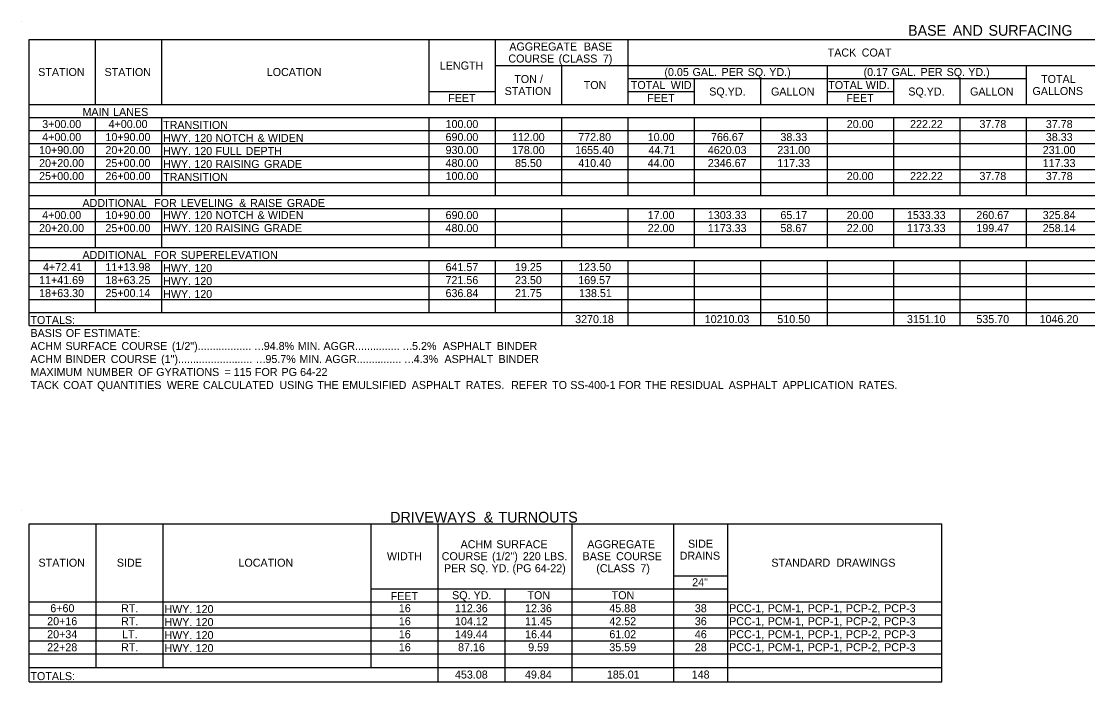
# Model space of a CAD drawing. Extents: x 1940653 to 1945779, y 534266 to 535271.
# Drawn here: x 1942440 to 1943159, y 534789 to 535235 of the extents above; entities that cross this region are included whole.
import ezdxf

# ---------------------------------------------------------------- set-up
doc = ezdxf.new("R2010")
doc.units = 0
doc.layers.add('Default', color=7, linetype='Continuous')
doc.layers.add('R_Logo', color=7, linetype='Continuous')

msp = doc.modelspace()

# ---------------------------------------------------------------- linework, layer by layer
at = {"layer": 'Default'}
for p, q in [((1942444.79, 535222.25), (1943743.93, 535222.25)), ((1942444.79, 535029.2), (1942444.79, 535222.25)), ((1942444.79, 535029.2), (1942444.79, 535222.25)), ((1942489.55, 535178.37), (1942489.55, 535222.25)), ((1942534.3, 535178.37), (1942534.3, 535222.25)), ((1942714.63, 535178.37), (1942714.63, 535222.25)), ((1942759.38, 535178.37), (1942759.38, 535222.25)), ((1942848.88, 535178.37), (1942848.88, 535222.25)), ((1942759.38, 535204.7), (1943743.93, 535204.7)), ((1942804.13, 535178.37), (1942804.13, 535204.7)), ((1942983.14, 535178.37), (1942983.14, 535204.7)), ((1943117.4, 535178.37), (1943117.4, 535204.7)), ((1942848.88, 535195.92), (1943117.4, 535195.92)), ((1942893.64, 535178.37), (1942893.64, 535195.92)), ((1942938.39, 535178.37), (1942938.39, 535195.92)), ((1943027.89, 535178.37), (1943027.89, 535195.92)), ((1943072.65, 535178.37), (1943072.65, 535195.92)), ((1942714.63, 535187.15), (1942759.38, 535187.15)), ((1942759.38, 535178.37), (1942759.38, 535187.15)), ((1942848.88, 535187.15), (1942893.64, 535187.15)), ((1942893.64, 535178.37), (1942893.64, 535187.15)), ((1942983.14, 535187.15), (1943027.89, 535187.15)), ((1943027.89, 535178.37), (1943027.89, 535187.15)), ((1942444.79, 535178.37), (1943743.93, 535178.37)), ((1942759.38, 535178.37), (1942893.64, 535178.37)), ((1942893.64, 535178.37), (1943027.89, 535178.37)), ((1943027.89, 535178.37), (1943072.65, 535178.37)), ((1943072.65, 535178.37), (1943206.9, 535178.37)), ((1942444.79, 535169.6), (1943743.93, 535169.6)), ((1942489.55, 535116.95), (1942489.55, 535169.6)), ((1942489.55, 535116.95), (1942489.55, 535169.6)), ((1942534.3, 535169.6), (1942714.63, 535169.6)), ((1942534.3, 535116.95), (1942534.3, 535169.6)), ((1942534.3, 535116.95), (1942534.3, 535169.6)), ((1942714.63, 535116.95), (1942714.63, 535169.6)), ((1942714.63, 535116.95), (1942714.63, 535169.6)), ((1942759.38, 535116.95), (1942759.38, 535169.6)), ((1942759.38, 535116.95), (1942759.38, 535169.6)), ((1942804.13, 535116.95), (1942804.13, 535169.6)), ((1942804.13, 535116.95), (1942804.13, 535169.6)), ((1942848.88, 535116.95), (1942848.88, 535169.6)), ((1942848.88, 535116.95), (1942848.88, 535169.6)), ((1942893.64, 535116.95), (1942893.64, 535169.6)), ((1942893.64, 535116.95), (1942893.64, 535169.6)), ((1942938.39, 535116.95), (1942938.39, 535169.6)), ((1942938.39, 535116.95), (1942938.39, 535169.6)), ((1942983.14, 535116.95), (1942983.14, 535169.6)), ((1942983.14, 535116.95), (1942983.14, 535169.6)), ((1943027.89, 535116.95), (1943027.89, 535169.6)), ((1943027.89, 535116.95), (1943027.89, 535169.6)), ((1943072.65, 535116.95), (1943072.65, 535169.6)), ((1943072.65, 535116.95), (1943072.65, 535169.6)), ((1943117.4, 535116.95), (1943117.4, 535169.6)), ((1943117.4, 535116.95), (1943117.4, 535169.6)), ((1942444.79, 535160.82), (1943743.93, 535160.82)), ((1942444.79, 535152.05), (1943743.93, 535152.05)), ((1942444.79, 535143.27), (1943743.93, 535143.27)), ((1942444.79, 535134.5), (1943743.93, 535134.5)), ((1942444.79, 535125.72), (1943743.93, 535125.72)), ((1942444.79, 535116.95), (1942893.64, 535116.95)), ((1942444.79, 535116.95), (1943743.93, 535116.95)), ((1942893.64, 535116.95), (1942983.14, 535116.95)), ((1942983.14, 535116.95), (1943027.89, 535116.95)), ((1943027.89, 535116.95), (1943162.15, 535116.95)), ((1942444.79, 535108.17), (1943743.93, 535108.17)), ((1942489.55, 535081.85), (1942489.55, 535108.17)), ((1942489.55, 535081.85), (1942489.55, 535108.17)), ((1942534.3, 535081.85), (1942534.3, 535108.17)), ((1942534.3, 535081.85), (1942534.3, 535108.17)), ((1942714.63, 535081.85), (1942714.63, 535108.17)), ((1942714.63, 535081.85), (1942714.63, 535108.17)), ((1942759.38, 535081.85), (1942759.38, 535108.17)), ((1942759.38, 535081.85), (1942759.38, 535108.17)), ((1942804.13, 535081.85), (1942804.13, 535108.17)), ((1942804.13, 535081.85), (1942804.13, 535108.17)), ((1942848.88, 535081.85), (1942848.88, 535108.17)), ((1942848.88, 535081.85), (1942848.88, 535108.17)), ((1942893.64, 535081.85), (1942893.64, 535108.17)), ((1942893.64, 535081.85), (1942893.64, 535108.17)), ((1942938.39, 535081.85), (1942938.39, 535108.17)), ((1942938.39, 535081.85), (1942938.39, 535108.17)), ((1942983.14, 535081.85), (1942983.14, 535108.17)), ((1942983.14, 535081.85), (1942983.14, 535108.17)), ((1943027.89, 535081.85), (1943027.89, 535108.17)), ((1943027.89, 535081.85), (1943027.89, 535108.17)), ((1943072.65, 535081.85), (1943072.65, 535108.17)), ((1943072.65, 535081.85), (1943072.65, 535108.17)), ((1943117.4, 535081.85), (1943117.4, 535108.17)), ((1943117.4, 535081.85), (1943117.4, 535108.17)), ((1942444.79, 535099.4), (1943743.93, 535099.4)), ((1942444.79, 535090.62), (1943743.93, 535090.62)), ((1942444.79, 535081.85), (1942848.88, 535081.85)), ((1942444.79, 535081.85), (1943743.93, 535081.85)), ((1942848.88, 535081.85), (1943117.4, 535081.85)), ((1943117.4, 535081.85), (1943564.92, 535081.85)), ((1942444.79, 535073.07), (1943743.93, 535073.07)), ((1942489.55, 535037.97), (1942489.55, 535073.07)), ((1942489.55, 535037.97), (1942489.55, 535073.07)), ((1942534.3, 535037.97), (1942534.3, 535073.07)), ((1942534.3, 535037.97), (1942534.3, 535073.07)), ((1942714.63, 535037.97), (1942714.63, 535073.07)), ((1942714.63, 535037.97), (1942714.63, 535073.07)), ((1942759.38, 535037.97), (1942759.38, 535073.07)), ((1942759.38, 535037.97), (1942759.38, 535073.07)), ((1942804.13, 535029.2), (1942804.13, 535073.07)), ((1942804.13, 535029.2), (1942804.13, 535073.07)), ((1942848.88, 535029.2), (1942848.88, 535073.07)), ((1942848.88, 535029.2), (1942848.88, 535073.07)), ((1942893.64, 535029.2), (1942893.64, 535073.07)), ((1942893.64, 535029.2), (1942893.64, 535073.07)), ((1942938.39, 535037.97), (1942938.39, 535073.07)), ((1942938.39, 535029.2), (1942938.39, 535073.07)), ((1942983.14, 535037.97), (1942983.14, 535073.07)), ((1942983.14, 535029.2), (1942983.14, 535073.07)), ((1943027.89, 535029.2), (1943027.89, 535073.07)), ((1943027.89, 535029.2), (1943027.89, 535073.07)), ((1943072.65, 535037.97), (1943072.65, 535073.07)), ((1943072.65, 535029.2), (1943072.65, 535073.07)), ((1943117.4, 535037.97), (1943117.4, 535073.07)), ((1943117.4, 535029.2), (1943117.4, 535073.07)), ((1942444.79, 535064.3), (1943743.93, 535064.3)), ((1942444.79, 535055.52), (1943743.93, 535055.52)), ((1942444.79, 535046.75), (1943743.93, 535046.75)), ((1942444.79, 535037.97), (1943743.93, 535037.97)), ((1942444.79, 535029.2), (1943743.93, 535029.2)), ((1942444.79, 534895.53), (1943060.36, 534895.53)), ((1942444.79, 534788.91), (1942444.79, 534895.53)), ((1942444.79, 534788.91), (1942444.79, 534895.53)), ((1942489.99, 534798.57), (1942489.99, 534895.53)), ((1942535.18, 534798.57), (1942535.18, 534895.53)), ((1942675.58, 534798.57), (1942675.58, 534895.53)), ((1942720.77, 534788.91), (1942720.77, 534895.53)), ((1942811.15, 534788.91), (1942811.15, 534895.53)), ((1942879.6, 534788.91), (1942879.6, 534895.53)), ((1942916.01, 534851.65), (1942916.01, 534895.53)), ((1942916.01, 534788.91), (1942916.01, 534895.53)), ((1943060.36, 534788.91), (1943060.36, 534895.53)), ((1943060.36, 534788.91), (1943060.36, 534895.53)), ((1942879.6, 534860.43), (1942916.01, 534860.43)), ((1942675.58, 534851.65), (1942879.6, 534851.65)), ((1942720.77, 534842.88), (1942720.77, 534851.65)), ((1942765.96, 534788.91), (1942765.96, 534851.65)), ((1942811.15, 534788.91), (1942811.15, 534851.65)), ((1942879.6, 534851.65), (1942916.01, 534851.65)), ((1942879.6, 534842.88), (1942879.6, 534851.65)), ((1942444.79, 534842.88), (1943060.36, 534842.88)), ((1942489.99, 534798.57), (1942489.99, 534842.88)), ((1942535.18, 534798.57), (1942535.18, 534842.88)), ((1942675.58, 534798.57), (1942675.58, 534842.88)), ((1942916.01, 534842.88), (1943060.36, 534842.88)), ((1942916.01, 534798.57), (1942916.01, 534842.88)), ((1942444.79, 534834.1), (1943060.36, 534834.1)), ((1942444.79, 534825.33), (1943060.36, 534825.33)), ((1942444.79, 534816.55), (1943060.36, 534816.55)), ((1942444.79, 534807.78), (1943060.36, 534807.78)), ((1942444.79, 534798.57), (1942765.96, 534798.57)), ((1942720.77, 534798.57), (1942765.96, 534798.57)), ((1942720.77, 534788.91), (1942720.77, 534798.57)), ((1942765.96, 534798.57), (1943060.36, 534798.57)), ((1942879.6, 534798.57), (1942916.01, 534798.57)), ((1942916.01, 534798.57), (1943060.36, 534798.57)), ((1942444.79, 534788.91), (1943060.36, 534788.91))]:
    msp.add_line(p, q, dxfattribs=at)
at = {"layer": 'R_Logo'}
for p, q in [((1942439.53, 535234.53), (1942439.53, 535234.53)), ((1942439.53, 534904.3), (1942439.53, 534904.3))]:
    msp.add_line(p, q, dxfattribs=at)

# ---------------------------------------------------------------- texts
at = {"layer": 'Default'}
for s, height, p in [('BASE', 7.2, (1943037.59, 535224.79)), (' AND', 7.2, (1943065.05, 535224.79)), (' SURFACING', 7.2, (1943089.14, 535224.79)), ('AGGREGATE', 5.4, (1942768.66, 535214.82)), (' BASE', 5.4, (1942816.92, 535214.82)), ('COURSE', 5.4, (1942768.02, 535206.72)), (' (CLASS', 5.4, (1942799.93, 535206.72)), (' 7)', 5.4, (1942829.74, 535206.72)), ('TACK', 5.4, (1942983.39, 535210.77)), (' COAT', 5.4, (1943004.33, 535210.77)), ('STATION', 5.4, (1942450.91, 535197.61)), ('STATION', 5.4, (1942495.67, 535197.61)), ('LOCATION', 5.4, (1942605.06, 535197.61)), ('LENGTH', 5.4, (1942721.78, 535202)), ('(0.05', 5.4, (1942873.26, 535197.61)), (' GAL.', 5.4, (1942890.22, 535197.61)), (' PER', 5.4, (1942909.82, 535197.61)), (' SQ.', 5.4, (1942927.4, 535197.61)), (' YD.)', 5.4, (1942941.97, 535197.61)), ('(0.17', 5.4, (1943007.57, 535197.61)), (' GAL.', 5.4, (1943024.43, 535197.61)), (' PER', 5.4, (1943044.03, 535197.61)), (' SQ.', 5.4, (1943061.6, 535197.61)), (' YD.)', 5.4, (1943076.17, 535197.61)), ('TON', 5.4, (1942771.99, 535192.88)), (' /', 5.4, (1942787.32, 535192.88)), ('TOTAL', 5.4, (1943127.31, 535192.88)), ('STATION', 5.4, (1942765.5, 535184.78)), ('TON', 5.4, (1942818.84, 535188.83)), ('TOTAL', 5.4, (1942850.61, 535188.83)), (' WID', 5.4, (1942875.53, 535188.83)), ('SQ.YD.', 5.4, (1942903.48, 535184.45)), ('GALLON', 5.4, (1942945.14, 535184.45)), ('TOTAL WID.', 5.4, (1942983.77, 535188.83)), ('SQ.YD.', 5.4, (1943037.74, 535184.45)), ('GALLON', 5.4, (1943079.4, 535184.45)), ('GALLONS', 5.4, (1943121.51, 535184.78)), ('FEET', 5.4, (1942727.44, 535180.06)), ('FEET', 5.4, (1942861.69, 535180.06)), ('FEET', 5.4, (1942995.95, 535180.06)), ('MAIN', 5.4, (1942480.77, 535170.68)), (' LANES', 5.4, (1942499.45, 535170.68)), ('3+00.00', 5.4, (1942453.62, 535162.51)), ('4+00.00', 5.4, (1942498.37, 535162.51)), ('TRANSITION', 5.4, (1942535.18, 535161.9)), ('100.00', 5.4, (1942725.65, 535162.51)), ('20.00', 5.4, (1942996.26, 535162.51)), ('222.22', 5.4, (1943038.94, 535162.51)), ('37.78', 5.4, (1943085.75, 535162.51)), ('37.78', 5.4, (1943130.51, 535162.51)), ('4+00.00', 5.4, (1942453.62, 535153.73)), ('10+90.00', 5.4, (1942496.27, 535153.73)), ('HWY.', 5.4, (1942535.18, 535153.13)), (' 120', 5.4, (1942554.22, 535153.13)), (' NOTCH', 5.4, (1942568.53, 535153.13)), (' &', 5.4, (1942596.84, 535153.13)), (' WIDEN', 5.4, (1942603.8, 535153.13)), ('690.00', 5.4, (1942725.65, 535153.73)), ('112.00', 5.4, (1942770.4, 535153.73)), ('772.80', 5.4, (1942815.16, 535153.73)), ('10.00', 5.4, (1942862, 535153.73)), ('766.67', 5.4, (1942904.65, 535153.73)), ('38.33', 5.4, (1942951.5, 535153.73)), ('38.33', 5.4, (1943130.51, 535153.73)), ('10+90.00', 5.4, (1942451.52, 535144.96)), ('20+20.00', 5.4, (1942496.27, 535144.96)), ('HWY.', 5.4, (1942535.18, 535144.35)), (' 120', 5.4, (1942554.22, 535144.35)), (' FULL', 5.4, (1942568.53, 535144.35)), (' DEPTH', 5.4, (1942588.81, 535144.35)), ('930.00', 5.4, (1942725.65, 535144.96)), ('178.00', 5.4, (1942770.4, 535144.96)), ('1655.40', 5.4, (1942813.06, 535144.96)), ('44.71', 5.4, (1942862.52, 535144.96)), ('4620.03', 5.4, (1942902.55, 535144.96)), ('231.00', 5.4, (1942949.41, 535144.96)), ('231.00', 5.4, (1943128.42, 535144.96)), ('20+20.00', 5.4, (1942451.52, 535136.18)), ('25+00.00', 5.4, (1942496.27, 535136.18)), ('HWY.', 5.4, (1942535.18, 535135.58)), (' 120', 5.4, (1942554.22, 535135.58)), (' RAISING', 5.4, (1942568.53, 535135.58)), (' GRADE', 5.4, (1942601.18, 535135.58)), ('480.00', 5.4, (1942725.65, 535136.18)), ('85.50', 5.4, (1942772.5, 535136.18)), ('410.40', 5.4, (1942815.16, 535136.18)), ('44.00', 5.4, (1942862, 535136.18)), ('2346.67', 5.4, (1942902.55, 535136.18)), ('117.33', 5.4, (1942949.4, 535136.18)), ('117.33', 5.4, (1943128.41, 535136.18)), ('25+00.00', 5.4, (1942451.52, 535127.41)), ('26+00.00', 5.4, (1942496.27, 535127.41)), ('TRANSITION', 5.4, (1942535.18, 535126.8)), ('100.00', 5.4, (1942725.65, 535127.41)), ('20.00', 5.4, (1942996.26, 535127.41)), ('222.22', 5.4, (1943038.94, 535127.41)), ('37.78', 5.4, (1943085.75, 535127.41)), ('37.78', 5.4, (1943130.51, 535127.41)), ('ADDITIONAL', 5.4, (1942480.77, 535109.25)), (' FOR', 5.4, (1942527.07, 535109.25)), (' LEVELING', 5.4, (1942545.06, 535109.25)), (' &', 5.4, (1942584.43, 535109.25)), (' RAISE', 5.4, (1942591.85, 535109.25)), (' GRADE', 5.4, (1942616.63, 535109.25)), ('4+00.00', 5.4, (1942453.62, 535101.08)), ('10+90.00', 5.4, (1942496.27, 535101.08)), ('HWY.', 5.4, (1942535.18, 535101.08)), (' 120', 5.4, (1942554.22, 535101.08)), (' NOTCH', 5.4, (1942568.53, 535101.08)), (' &', 5.4, (1942596.84, 535101.08)), (' WIDEN', 5.4, (1942603.8, 535101.08)), ('690.00', 5.4, (1942725.65, 535101.08)), ('17.00', 5.4, (1942862, 535101.08)), ('1303.33', 5.4, (1942902.55, 535101.08)), ('65.17', 5.4, (1942951.5, 535101.08)), ('20.00', 5.4, (1942996.26, 535101.08)), ('1533.33', 5.4, (1943036.81, 535101.08)), ('260.67', 5.4, (1943083.66, 535101.08)), ('325.84', 5.4, (1943128.42, 535101.08)), ('20+20.00', 5.4, (1942451.52, 535092.31)), ('25+00.00', 5.4, (1942496.27, 535092.31)), ('HWY.', 5.4, (1942535.18, 535092.31)), (' 120', 5.4, (1942554.22, 535092.31)), (' RAISING', 5.4, (1942568.53, 535092.31)), (' GRADE', 5.4, (1942601.18, 535092.31)), ('480.00', 5.4, (1942725.65, 535092.31)), ('22.00', 5.4, (1942862, 535092.31)), ('1173.33', 5.4, (1942902.55, 535092.31)), ('58.67', 5.4, (1942951.5, 535092.31)), ('22.00', 5.4, (1942996.26, 535092.31)), ('1173.33', 5.4, (1943036.81, 535092.31)), ('199.47', 5.4, (1943083.66, 535092.31)), ('258.14', 5.4, (1943128.42, 535092.31)), ('ADDITIONAL', 5.4, (1942480.77, 535074.15)), (' FOR', 5.4, (1942527.07, 535074.15)), (' SUPERELEVATION', 5.4, (1942545.06, 535074.15)), ('4+72.41', 5.4, (1942454.13, 535065.98)), ('11+13.98', 5.4, (1942496.26, 535065.98)), ('HWY.', 5.4, (1942535.18, 535065.38)), (' 120', 5.4, (1942554.22, 535065.38)), ('641.57', 5.4, (1942725.64, 535065.98)), ('19.25', 5.4, (1942772.47, 535065.98)), ('123.50', 5.4, (1942815.16, 535065.98)), ('11+41.69', 5.4, (1942451.51, 535057.21)), ('18+63.25', 5.4, (1942496.24, 535057.21)), ('HWY.', 5.4, (1942535.18, 535056.6)), (' 120', 5.4, (1942554.22, 535056.6)), ('721.56', 5.4, (1942725.64, 535057.21)), ('23.50', 5.4, (1942772.5, 535057.21)), ('169.57', 5.4, (1942815.14, 535057.21)), ('18+63.30', 5.4, (1942451.52, 535048.43)), ('25+00.14', 5.4, (1942496.27, 535048.43)), ('HWY.', 5.4, (1942535.18, 535047.83)), (' 120', 5.4, (1942554.22, 535047.83)), ('636.84', 5.4, (1942725.65, 535048.43)), ('21.75', 5.4, (1942772.47, 535048.43)), ('138.51', 5.4, (1942815.67, 535048.43)), ('TOTALS:', 5.4, (1942445.67, 535030.28)), ('3270.18', 5.4, (1942813.05, 535030.88)), ('10210.03', 5.4, (1942900.45, 535030.88)), ('510.50', 5.4, (1942949.42, 535030.88)), ('3151.10', 5.4, (1943036.82, 535030.88)), ('535.70', 5.4, (1943083.67, 535030.88)), ('1046.20', 5.4, (1943126.33, 535030.88)), ('BASIS', 5.4, (1942445.67, 535021.5)), (' OF', 5.4, (1942467.51, 535021.5)), (' ESTIMATE:', 5.4, (1942479.73, 535021.5)), ('ACHM', 5.4, (1942445.67, 535012.73)), (' SURFACE', 5.4, (1942467.32, 535012.73)), (' COURSE', 5.4, (1942505.07, 535012.73)), (' (1/2")..................', 5.4, (1942539.05, 535012.73)), ('94.8%', 5.4, (1942603.04, 535012.73)), (' MIN.', 5.4, (1942623.95, 535012.73)), (' AGGR...............', 5.4, (1942641.31, 535012.73)), ('5.2%', 5.4, (1942703.06, 535012.73)), ('  ASPHALT', 5.4, (1942719.78, 535012.73)), (' BINDER', 5.4, (1942758.2, 535012.73)), ('ACHM', 5.4, (1942445.67, 535003.95)), (' BINDER', 5.4, (1942467.32, 535003.95)), (' COURSE', 5.4, (1942497.82, 535003.95)), (' (1").........................', 5.4, (1942531.8, 535003.95)), ('…', 5.4, (1942596.38, 535012.73)), ('95.7%', 5.4, (1942604.16, 535003.95)), (' MIN.', 5.4, (1942625.08, 535003.95)), (' AGGR...............', 5.4, (1942642.44, 535003.95)), ('…', 5.4, (1942696.4, 535012.73)), ('4.3%', 5.4, (1942704.18, 535003.95)), ('  ASPHALT', 5.4, (1942720.91, 535003.95)), (' BINDER', 5.4, (1942759.33, 535003.95)), ('…', 5.4, (1942597.51, 535003.95)), ('…', 5.4, (1942697.52, 535003.95)), ('MAXIMUM', 5.4, (1942445.67, 534995.18)), (' NUMBER', 5.4, (1942481.57, 534995.18)), (' OF', 5.4, (1942516.26, 534995.18)), (' GYRATIONS', 5.4, (1942528.49, 534995.18)), (' =', 5.4, (1942574.63, 534995.18)), (' 115', 5.4, (1942580.71, 534995.18)), (' FOR', 5.4, (1942595.09, 534995.18)), (' PG', 5.4, (1942613.01, 534995.18)), (' 64-22', 5.4, (1942625.53, 534995.18)), ('TACK', 5.4, (1942445.67, 534986.4)), (' COAT', 5.4, (1942465.78, 534986.4)), (' QUANTITIES', 5.4, (1942488.69, 534986.4)), (' WERE', 5.4, (1942535.66, 534986.4)), (' CALCULATED', 5.4, (1942559.99, 534986.4)), (' USING', 5.4, (1942611.58, 534986.4)), (' THE', 5.4, (1942637.1, 534986.4)), (' EMULSIFIED', 5.4, (1942653.88, 534986.4)), (' ASPHALT', 5.4, (1942700.85, 534986.4)), (' RATES.', 5.4, (1942737.19, 534986.4)), ('  REFER', 5.4, (1942765.88, 534986.4)), (' TO', 5.4, (1942795.54, 534986.4)), (' SS-400-1', 5.4, (1942807.78, 534986.4)), (' FOR', 5.4, (1942840.35, 534986.4)), (' THE', 5.4, (1942858.27, 534986.4)), (' RESIDUAL', 5.4, (1942875.05, 534986.4)), (' ASPHALT', 5.4, (1942914.62, 534986.4)), (' APPLICATION', 5.4, (1942950.95, 534986.4)), (' RATES.', 5.4, (1943002.32, 534986.4)), ('DRIVEWAYS', 7.2, (1942688.31, 534896.32)), (' &', 7.2, (1942748.75, 534896.32)), (' TURNOUTS', 7.2, (1942758.65, 534896.32)), ('ACHM', 5.4, (1942735.81, 534878.99)), (' SURFACE', 5.4, (1942757.91, 534878.99)), ('AGGREGATE', 5.4, (1942821.24, 534878.99)), ('SIDE', 5.4, (1942889.18, 534879.33)), ('STATION', 5.4, (1942451.13, 534866.5)), ('SIDE', 5.4, (1942503.96, 534866.5)), ('LOCATION', 5.4, (1942585.98, 534866.5)), ('WIDTH', 5.4, (1942686.1, 534870.89)), ('COURSE', 5.4, (1942723.08, 534870.89)), (' (1/2")', 5.4, (1942754.99, 534870.89)), (' 220', 5.4, (1942775.77, 534870.89)), (' LBS.', 5.4, (1942790.08, 534870.89)), ('BASE', 5.4, (1942818.07, 534870.89)), (' COURSE', 5.4, (1942838.67, 534870.89)), ('DRAINS', 5.4, (1942883.53, 534871.23)), ('STANDARD', 5.4, (1942945.38, 534866.5)), (' DRAWINGS', 5.4, (1942987.35, 534866.5)), ('PER', 5.4, (1942724.58, 534862.79)), (' SQ.', 5.4, (1942740.06, 534862.79)), (' YD.', 5.4, (1942754.63, 534862.79)), (' (PG', 5.4, (1942768.79, 534862.79)), (' 64-22)', 5.4, (1942783.84, 534862.79)), ('(CLASS', 5.4, (1942827.31, 534862.79)), (' 7)', 5.4, (1942855.03, 534862.79)), ('24"', 5.4, (1942892.01, 534853.34)), ('FEET', 5.4, (1942688.61, 534843.96)), ('SQ.', 5.4, (1942730.05, 534844.57)), (' YD.', 5.4, (1942742.53, 534844.57)), ('TON', 5.4, (1942780.89, 534844.57)), ('TON', 5.4, (1942837.71, 534844.57)), ('6+60', 5.4, (1942459.08, 534835.79)), ('RT.', 5.4, (1942506.83, 534835.79)), ('HWY.', 5.4, (1942536.05, 534835.18)), (' 120', 5.4, (1942555.09, 534835.18)), ('16', 5.4, (1942694.15, 534835.79)), ('112.36', 5.4, (1942732, 534835.79)), ('12.36', 5.4, (1942779.29, 534835.79)), ('45.88', 5.4, (1942836.1, 534835.79)), ('38', 5.4, (1942893.78, 534835.79)), ('PCC-1,', 5.4, (1942916.89, 534835.79)), (' PCM-1,', 5.4, (1942940.95, 534835.79)), (' PCP-1,', 5.4, (1942967.94, 534835.79)), (' PCP-2,', 5.4, (1942993.68, 534835.79)), (' PCP-3', 5.4, (1943019.42, 534835.79)), ('20+16', 5.4, (1942456.97, 534827.02)), ('RT.', 5.4, (1942506.83, 534827.02)), ('HWY.', 5.4, (1942536.05, 534826.41)), (' 120', 5.4, (1942555.09, 534826.41)), ('16', 5.4, (1942694.15, 534827.02)), ('104.12', 5.4, (1942732.03, 534827.02)), ('11.45', 5.4, (1942779.27, 534827.02)), ('42.52', 5.4, (1942836.14, 534827.02)), ('36', 5.4, (1942893.78, 534827.02)), ('PCC-1,', 5.4, (1942916.89, 534827.02)), (' PCM-1,', 5.4, (1942940.95, 534827.02)), (' PCP-1,', 5.4, (1942967.94, 534827.02)), (' PCP-2,', 5.4, (1942993.68, 534827.02)), (' PCP-3', 5.4, (1943019.42, 534827.02)), ('20+34', 5.4, (1942456.98, 534818.24)), ('LT.', 5.4, (1942507.46, 534818.24)), ('HWY.', 5.4, (1942536.05, 534817.63)), (' 120', 5.4, (1942555.09, 534817.63)), ('16', 5.4, (1942694.15, 534818.24)), ('149.44', 5.4, (1942732.01, 534818.24)), ('16.44', 5.4, (1942779.3, 534818.24)), ('61.02', 5.4, (1942836.14, 534818.24)), ('46', 5.4, (1942893.78, 534818.24)), ('PCC-1,', 5.4, (1942916.89, 534818.24)), (' PCM-1,', 5.4, (1942940.95, 534818.24)), (' PCP-1,', 5.4, (1942967.94, 534818.24)), (' PCP-2,', 5.4, (1942993.68, 534818.24)), (' PCP-3', 5.4, (1943019.42, 534818.24)), ('22+28', 5.4, (1942456.97, 534809.47)), ('RT.', 5.4, (1942506.83, 534809.47)), ('HWY.', 5.4, (1942536.05, 534808.86)), (' 120', 5.4, (1942555.09, 534808.86)), ('16', 5.4, (1942694.15, 534809.47)), ('87.16', 5.4, (1942734.1, 534809.47)), ('9.59', 5.4, (1942781.38, 534809.47)), ('35.59', 5.4, (1942836.1, 534809.47)), ('28', 5.4, (1942893.78, 534809.47)), ('PCC-1,', 5.4, (1942916.89, 534809.47)), (' PCM-1,', 5.4, (1942940.95, 534809.47)), (' PCP-1,', 5.4, (1942967.94, 534809.47)), (' PCP-2,', 5.4, (1942993.68, 534809.47)), (' PCP-3', 5.4, (1943019.42, 534809.47)), ('TOTALS:', 5.4, (1942445.67, 534789.99)), ('453.08', 5.4, (1942732, 534791.04)), ('49.84', 5.4, (1942779.21, 534791.04)), ('185.01', 5.4, (1942834.45, 534791.04)), ('148', 5.4, (1942891.68, 534791.04))]:
    msp.add_text(s, height=height, dxfattribs=at).set_placement(p)

doc.saveas('drawing.dxf')
